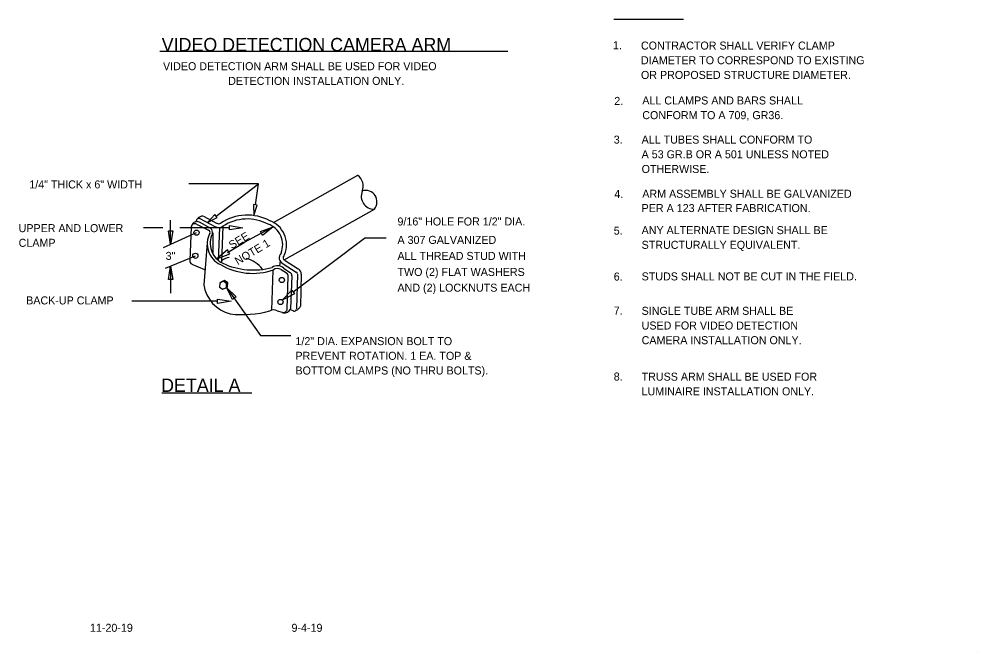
# Model space of a CAD drawing. Extents: x 12.4 to 19.6, y 6 to 16.3.
# Drawn here: x 12.44 to 19.62, y 5.98 to 10.73 of the extents above; entities that cross this region are included whole.
import ezdxf

# ---------------------------------------------------------------- set-up
doc = ezdxf.new("R2010")
doc.units = 0
for name, color, linetype in [('DETL-DIMS', 7, 'Continuous'), ('DETL-LINE', 7, 'Continuous'), ('DETL-NOTE', 7, 'Continuous'), ('DETL-TITL', 7, 'Continuous'), ('TTLB-TEXT', 7, 'Continuous')]:
    doc.layers.add(name, color=color, linetype=linetype)

msp = doc.modelspace()

# ---------------------------------------------------------------- linework, layer by layer
at = {"layer": 'DETL-DIMS'}
for p, q in [((14.2285, 9.4974), (13.7065, 9.4974)), ((13.9105, 9.2564), (14.2285, 9.4974)), ((14.2065, 9.3404), (14.2285, 9.4974)), ((13.5705, 9.0444), (13.5705, 9.2254)), ((13.5125, 9.1694), (13.3675, 9.1694)), ((13.5175, 9.0204), (13.7645, 9.1324)), ((14.0105, 9.1694), (13.6385, 9.1694)), ((14.3395, 9.1764), (14.1205, 9.0594)), ((13.9975, 8.9844), (14.1205, 9.0594)), ((14.4878, 8.6877), (15.0237, 9.0919)), ((15.1865, 9.0919), (15.0237, 9.0919)), ((13.5325, 8.8654), (13.7555, 8.9594)), ((13.5705, 8.8814), (13.5705, 8.6794)), ((13.9881, 8.7219), (14.2451, 8.3622)), ((13.9225, 8.6184), (13.2795, 8.6184)), ((14.2451, 8.3622), (14.4701, 8.3622))]:
    msp.add_line(p, q, dxfattribs=at)
for points in [[(14.2195, 9.3384), (14.1925, 9.3424), (14.1945, 9.2604)], [(13.9185, 9.2464), (13.9025, 9.2674), (13.8455, 9.2084)], [(13.5535, 9.1454), (13.5875, 9.1454), (13.5705, 9.0444)], [(14.0105, 9.1524), (14.0105, 9.1864), (14.1115, 9.1694)], [(14.2595, 9.1114), (14.2435, 9.1404), (14.3395, 9.1764)], [(14.0135, 8.9734), (13.9975, 9.0024), (13.9175, 8.9374)], [(13.5875, 8.7804), (13.5535, 8.7804), (13.5705, 8.8814)], [(14.0618, 8.6508), (14.0348, 8.6308), (13.9881, 8.7219)], [(14.4786, 8.7006), (14.4982, 8.6742), (14.4068, 8.6275)], [(13.9225, 8.6014), (13.9225, 8.6344), (14.0235, 8.6184)]]:
    msp.add_lwpolyline(points, close=True, dxfattribs=at)
at = {"layer": 'DETL-LINE'}
for p, q in [((14.3425, 9.2084), (14.9725, 9.5624)), ((14.4215, 8.9284), (15.0975, 9.3084)), ((13.7615, 9.2184), (13.7655, 9.2284)), ((13.8715, 9.1634), (13.7855, 9.2114)), ((13.7885, 9.2374), (13.9015, 9.1794)), ((13.8155, 9.2564), (13.9145, 9.2044)), ((13.7245, 9.1724), (13.7135, 8.9244)), ((13.7645, 9.1964), (13.8545, 9.1504)), ((13.8855, 9.1314), (13.8865, 8.9754)), ((13.9355, 9.1704), (13.9275, 8.9214)), ((13.9615, 9.1794), (13.9505, 8.9134)), ((13.8475, 9.0854), (13.8185, 8.7414)), ((14.3905, 8.9204), (14.3865, 8.8834)), ((14.4295, 8.9234), (14.4255, 8.9254)), ((14.4295, 8.9234), (14.5275, 8.8614)), ((13.7295, 8.8974), (13.8235, 8.8554)), ((14.3285, 8.5524), (14.3385, 8.8524)), ((14.3985, 8.8554), (14.4385, 8.8304)), ((14.4145, 8.8994), (14.5125, 8.8374)), ((14.4175, 8.8654), (14.4655, 8.8344)), ((13.9647, 8.7684), (13.9379, 8.7549)), ((13.9739, 8.7735), (13.9471, 8.7601)), ((13.9647, 8.7684), (13.9739, 8.7735)), ((13.9898, 8.7519), (13.9647, 8.7684)), ((13.999, 8.757), (13.9739, 8.7735)), ((14.4435, 8.5614), (14.4515, 8.8054)), ((14.4785, 8.8094), (14.4685, 8.5604)), ((14.5205, 8.8224), (14.5145, 8.5604)), ((14.5485, 8.8224), (14.5435, 8.5804)), ((13.9379, 8.7549), (13.9362, 8.725)), ((13.9362, 8.725), (13.9612, 8.7085)), ((13.9379, 8.7549), (13.9471, 8.7601)), ((13.9612, 8.7085), (13.9881, 8.7219)), ((13.9881, 8.7219), (13.9898, 8.7519)), ((13.9881, 8.7219), (13.9972, 8.7271)), ((13.9898, 8.7519), (13.999, 8.757)), ((13.9972, 8.7271), (13.999, 8.757)), ((14.4685, 8.5554), (14.4905, 8.5454)), ((14.3695, 8.5464), (14.4075, 8.5354))]:
    msp.add_line(p, q, dxfattribs=at)
for centre in [(13.7643, 9.1323), (13.7556, 8.959), (14.4044, 8.7774), (14.3937, 8.6131)]:
    msp.add_circle(centre, 0.0195, dxfattribs=at)
for centre, radius, start, end in [((14.9122, 9.4804), 0.1017, 337.81628, 53.98655), ((15.0964, 9.4053), 0.0972, 157.81628, 270.90248), ((15.0304, 9.3627), 0.0868, 321.05501, 104.90869), ((13.7521, 9.171), 0.0281, 62.83784, 177.57877), ((13.768, 9.1746), 0.0409, 64.23663, 165.05705), ((13.7809, 9.2225), 0.0169, 62.71568, 159.76593), ((13.8109, 9.2074), 0.0489, 84.70391, 144.51391), ((13.9313, 9.2242), 0.0251, 236.72503, 305.30783), ((14.1449, 8.9025), 0.3611, 62.1088, 123.30246), ((14.1449, 8.9025), 0.3323, 62.1088, 123.30246), ((14.2473, 9.0422), 0.1917, 337.34319, 70.97204), ((14.0171, 9.0491), 0.1724, 152.86771, 244.57452), ((13.8507, 9.1355), 0.0151, 329.07168, 76.564), ((13.8448, 9.1335), 0.0397, 348.10516, 48.32479), ((13.9313, 9.2242), 0.0539, 236.72503, 305.30783), ((14.2473, 9.0422), 0.1629, 337.34319, 70.97204), ((14.0331, 9.0525), 0.1662, 154.02634, 244.3188), ((13.7417, 8.9234), 0.0281, 177.57877, 245.33962), ((14.0628, 8.7403), 0.2139, 104.751, 120.54162), ((14.086, 8.7316), 0.2139, 36.30193, 75.97134), ((14.4331, 8.9449), 0.0495, 135.76408, 247.89654), ((14.4331, 8.9449), 0.0207, 135.76408, 247.89654), ((14.4549, 8.9416), 0.0407, 138.94798, 154.15929), ((14.1857, 9.3068), 0.4793, 239.59378, 288.89798), ((14.1897, 9.4007), 0.5479, 245.33933, 284.91007), ((14.3709, 8.8183), 0.0665, 45.2238, 127.28178), ((14.3714, 8.8102), 0.0528, 58.56861, 125.25461), ((14.5033, 8.823), 0.0456, 358.72582, 57.74154), ((14.4236, 8.8062), 0.0281, 358.15403, 57.57656), ((14.4505, 8.8109), 0.0281, 357.68903, 57.099), ((14.5033, 8.823), 0.0169, 358.72582, 57.74154), ((14.081, 8.7814), 0.2651, 188.62571, 256.17677), ((14.3424, 8.5014), 0.0528, 58.56861, 125.25461), ((14.4157, 8.5618), 0.0281, 252.93299, 358.15403), ((14.426, 8.5771), 0.0458, 255.56419, 338.06073), ((14.4974, 8.5604), 0.0169, 244.45138, 358.72582), ((14.4889, 8.6059), 0.0601, 293.72685, 335.28255), ((14.1088, 9.256), 0.7378, 262.90557, 286.12723)]:
    msp.add_arc(centre, radius, start, end, dxfattribs=at)
at = {"layer": 'DETL-NOTE'}
msp.add_line((16.8915, 10.7316), (17.4153, 10.7316), dxfattribs=at)
at = {"layer": 'DETL-TITL'}
for p, q in [((13.4889, 10.4909), (16.0985, 10.4909)), ((13.5051, 7.9333), (14.1801, 7.9333))]:
    msp.add_line(p, q, dxfattribs=at)
at = {"layer": 'TTLB-TEXT'}
msp.add_line((19.6208, 5.9844), (19.6208, 5.9844), dxfattribs=at)

# ---------------------------------------------------------------- texts
at = {"layer": 'DETL-NOTE'}
for s, p in [('1. ', (16.8857, 10.5064)), ('CONTRACTOR SHALL VERIFY CLAMP', (17.0957, 10.5039)), ('DIAMETER TO CORRESPOND TO EXISTING', (17.0957, 10.3939)), ('VIDEO DETECTION ARM SHALL BE USED FOR VIDEO ', (13.5132, 10.3493)), ('DETECTION INSTALLATION ONLY.', (14.0016, 10.2393)), ('OR PROPOSED STRUCTURE DIAMETER.', (17.0957, 10.2839)), ('2. ', (16.8957, 10.0894)), ('ALL CLAMPS AND BARS SHALL', (17.1057, 10.0926)), ('CONFORM TO A 709, GR36.', (17.1057, 9.9826)), ('3. ', (16.8917, 9.7994)), ('ALL TUBES SHALL CONFORM TO', (17.1007, 9.7994)), ('A 53 GR.B OR A 501 UNLESS NOTED', (17.1007, 9.6894)), ('OTHERWISE.', (17.1007, 9.5794)), ('1/4" THICK x 6" WIDTH', (12.5109, 9.4635)), ('4. ', (16.8957, 9.3914)), ('ARM ASSEMBLY SHALL BE GALVANIZED', (17.1057, 9.3938)), ('PER A 123 AFTER FABRICATION.', (17.1007, 9.2864)), ('9/16" HOLE FOR 1/2" DIA.', (15.2707, 9.186)), ('UPPER AND LOWER', (12.4309, 9.1361)), ('5. ', (16.8917, 9.1174)), ('ANY ALTERNATE DESIGN SHALL BE', (17.1007, 9.1211)), ('CLAMP', (12.4309, 9.0261)), ('A 307 GALVANIZED', (15.2707, 9.048)), ('STRUCTURALLY EQUIVALENT.', (17.1007, 9.0111)), ('3"', (13.5328, 8.9283)), ('ALL THREAD STUD WITH', (15.2707, 8.928)), ('TWO (2) FLAT WASHERS', (15.2707, 8.808)), ('6. ', (16.8917, 8.7734)), ('STUDS SHALL NOT BE CUT IN THE FIELD.', (17.1007, 8.7745)), ('AND (2) LOCKNUTS EACH', (15.2707, 8.69)), ('BACK-UP CLAMP', (12.4876, 8.5946)), ('7. ', (16.8917, 8.5184)), ('SINGLE TUBE ARM SHALL BE', (17.1007, 8.5166)), ('USED FOR VIDEO DETECTION', (17.1007, 8.4066)), ('1/2" DIA. EXPANSION BOLT TO ', (14.506, 8.2896)), ('CAMERA INSTALLATION ONLY.', (17.1007, 8.2966)), ('PREVENT ROTATION. 1 EA. TOP & ', (14.506, 8.1796)), ('BOTTOM CLAMPS (NO THRU BOLTS).', (14.506, 8.0696)), ('8.', (16.8917, 8.0244)), ('TRUSS ARM SHALL BE USED FOR', (17.1007, 8.0234)), ('LUMINAIRE INSTALLATION ONLY.', (17.1007, 7.9134))]:
    msp.add_text(s, height=0.06, dxfattribs=at).set_placement(p)
for s, p in [('SEE', (14.0288, 9.0074)), ('NOTE 1', (14.0738, 8.8874))]:
    msp.add_text(s, height=0.06, rotation=31.10838, dxfattribs=at).set_placement(p)
at = {"layer": 'DETL-TITL'}
for s, p in [('VIDEO DETECTION CAMERA ARM', (13.5034, 10.4911)), ('DETAIL A', (13.4991, 7.939))]:
    msp.add_text(s, height=0.1, dxfattribs=at).set_placement(p)
at = {"layer": 'TTLB-TEXT'}
for s, p in [('11-20-19', (12.9657, 6.1419)), ('9-4-19', (14.4764, 6.1419))]:
    msp.add_text(s, height=0.06, dxfattribs=at).set_placement(p)

doc.saveas('drawing.dxf')
